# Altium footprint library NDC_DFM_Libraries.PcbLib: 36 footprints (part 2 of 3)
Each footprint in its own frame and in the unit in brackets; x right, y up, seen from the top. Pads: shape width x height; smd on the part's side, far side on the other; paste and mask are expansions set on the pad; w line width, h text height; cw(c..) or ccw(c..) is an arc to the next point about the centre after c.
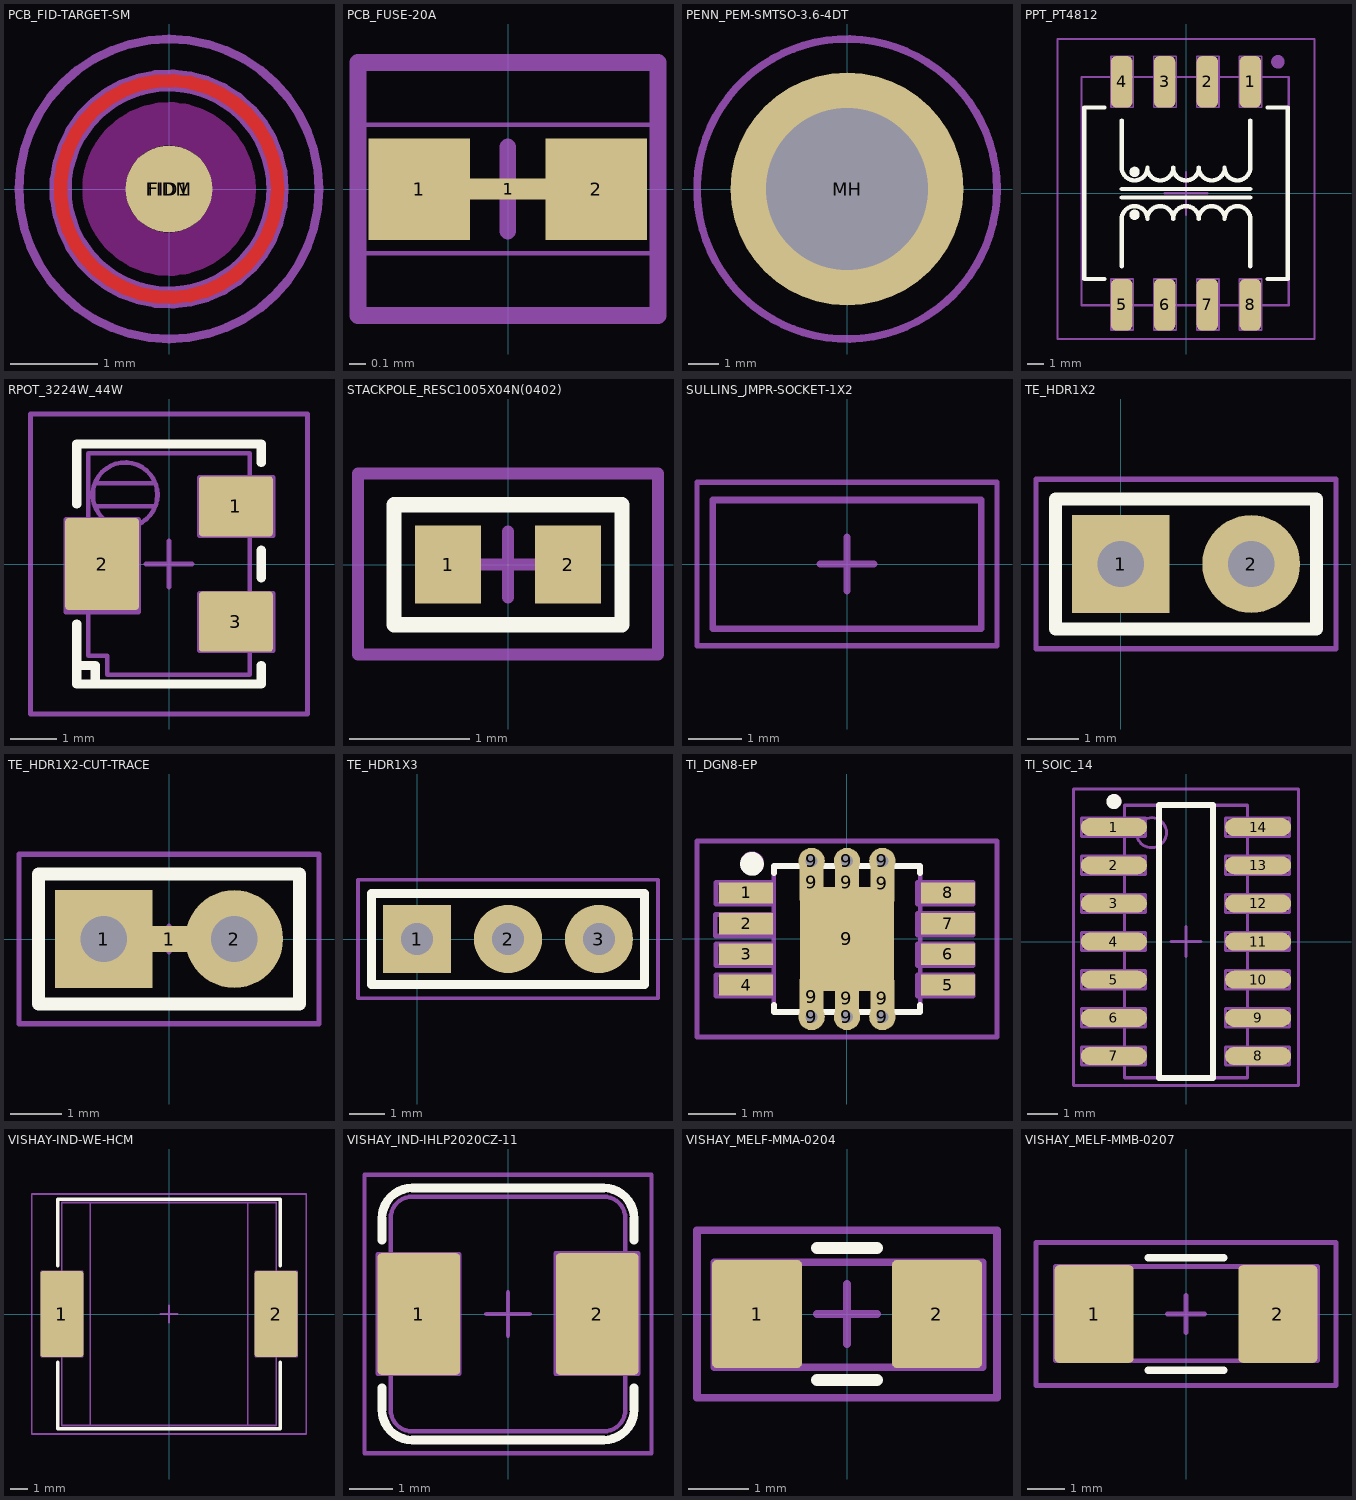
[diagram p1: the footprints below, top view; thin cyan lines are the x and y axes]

## PCB_FID-TARGET-SM [mm]
pads (2):
  round 1 on Mech6 paste-0.55 mask+1: FID1(0,0)
  round 1 all layers, no hole paste-0.762 mask+0.9: FIDM(0,0)
Top Layer:
  circle w0.155: c0,0 r1.25
Bottom Layer:
  circle w0.155: c0,0 r1.25
Keep-Out Layer:
  circle w0.5: c0,0 r0.75
M06 - ASSY TOP:
  circle w0.254: c0,0 r1.25
  text ".designator" at -1.194,-2.819 h0.89
M15 - COURTYARD TOP:
  circle w0.1: c0,0 r1.727
  lines w0.1: -0.381,0 0.381,0 ; 0,-0.381 0,0.381

## PCB_FUSE-20A [mm]
pads (3):
  rect 0.6x0.6 smd: 1(-0.527,-0.001) 2(0.523,-0.001)
  rrect10% 1x0.125 smd paste-2 mask-2: 1(0,0)
M06 - ASSY TOP:
  lines w0.025: -0.889,-0.381 0.889,-0.381 0.889,0.381 -0.889,0.381 -0.889,-0.381
  text "DNP" at -0.254,-0.711 h0.25
  text ".designator" at -0.737,-0.254 h0.89
M15 - COURTYARD TOP:
  lines w0.1: -0.254,0 0.254,0 ; -0.002,-0.249 -0.002,0.249 ; -0.889,-0.75 0.889,-0.75 0.889,0.75 -0.889,0.75 -0.889,-0.75

## PENN_PEM-SMTSO-3.6-4DT [mm] "PEM Standoff SMTSO-3.6-4DT, Matte Tin, Surface Mount Solder, ReelFast"
height 4
pads (1):
  round 7.77 hole 5.41: MH(0,0)
M06 - ASSY TOP:
  circle w0.254: c0,0 r2.7
  circle w0.254: c0,0 r3.57
  text ".designator" at -1.88,-0.432 h0.89
M15 - COURTYARD TOP:
  circle w0.254: c0,0 r5
  lines w0.1: -0.5,0 0.5,0 ; 0,-0.5 0,0.5
3D body: height 4, standoff -1.53, extent -3.57,-3.57 3.57,3.57

## PPT_PT4812 [mm] "Transformer for Digital Audio Data Transmission"
height 9.15
pads (8):
  rrect50% 1.27x3.05 smd: 1(3.81,6.605) 2(1.27,6.605) 3(-1.27,6.605) 4(-3.81,6.605) 5(-3.81,-6.605) 6(-1.27,-6.605) 7(1.27,-6.605) 8(3.81,-6.605)
Top Overlay:
  circle w0.254: c-3.048,1.271 r0.18
  circle w0.254: c-3.048,-1.269 r0.18
  lines w0.254: -4.826,-5.081 -6.03,-5.081 -6.03,5.081 -4.826,5.081 ; -3.81,-4.317 -3.81,-1.523 cw(c-3.048,-1.523) -3.048,-0.761 cw(c-3.048,-1.523) -2.286,-1.523 cw(c-1.524,-1.523) -1.524,-0.761 cw(c-1.524,-1.523) -0.762,-1.523 cw(c0,-1.523) 0,-0.761 cw(c0,-1.523) 0.762,-1.523 cw(c1.524,-1.523) 1.524,-0.761 cw(c1.524,-1.523) 2.286,-1.523 cw(c3.048,-1.523) 3.048,-0.761 cw(c3.048,-1.523) 3.81,-1.523 3.81,-4.317 ; -3.81,0.255 3.81,0.255 ; -3.81,4.319 -3.81,1.525 ccw(c-3.048,1.525) -3.048,0.763 ccw(c-3.048,1.525) -2.286,1.525 ccw(c-1.524,1.525) -1.524,0.763 ccw(c-1.524,1.525) -0.762,1.525 ccw(c0,1.525) 0,0.763 ccw(c0,1.525) 0.762,1.525 ccw(c1.524,1.525) 1.524,0.763 ccw(c1.524,1.525) 2.286,1.525 ccw(c3.048,1.525) 3.048,0.763 ccw(c3.048,1.525) 3.81,1.525 3.81,4.319 ; -3.228,-1.269 -2.921,-1.269 ; -3.228,1.271 -2.921,1.271 ; 3.302,-0.253 -3.81,-0.253 3.81,-0.253 ; 4.826,-5.081 6.03,-5.081 6.03,5.081 4.826,5.081
M06 - ASSY TOP:
  circle w0.4: c5.448,7.791 r0.2
  lines w0.1: -4.445,-8.105 -4.445,-5.082 -3.124,-5.082 -3.124,-8.105 -4.445,-8.105 ; -4.445,5.105 -3.124,5.105 -3.124,8.128 -4.445,8.128 -4.445,5.105 ; -1.905,-8.105 -1.905,-5.082 -0.584,-5.082 -0.584,-8.105 -1.905,-8.105 ; -1.905,5.105 -1.905,8.128 -0.584,8.128 -0.584,5.105 -1.905,5.105 ; 0.635,-8.105 0.635,-5.082 1.956,-5.082 1.956,-8.105 0.635,-8.105 ; 0.635,5.105 0.635,8.128 1.956,8.128 1.956,5.105 0.635,5.105 ; 3.175,-8.105 3.175,-5.082 4.496,-5.082 4.496,-8.105 3.175,-8.105 ; 3.175,5.105 3.175,8.128 4.496,8.128 4.496,5.105 3.175,5.105
  lines w0.127: -6.198,-6.638 -6.198,6.894 6.091,6.894 6.091,-6.638 -6.198,-6.638
  text ".designator" at -4.115,-0.483 h0.89
M15 - COURTYARD TOP:
  lines w0.127: -1.27,0 1.27,0 ; 0,-1.27 0,1.27 ; -7.62,-8.635 -7.62,9.145 7.62,9.145 7.62,-8.635 -7.62,-8.635
3D body: height 8.86, standoff 0.02, extent -5.969,-6.638 6.091,6.894

## RPOT_3224W_44W [mm] "Potentiometer, SMT 4mm, Multiturn Cermet, Sealed"
height 5.3
pads (3):
  rrect10% 1.6x1.3 smd: 1(1.45,1.25) 3(1.45,-1.25)
  rrect10% 1.6x2 smd: 2(-1.45,0)
Top Overlay:
  lines w0.2: -2,-2.2 -1.6,-2.2 -1.6,-2.6 ; -2,-1.3 -2,-2.6 2,-2.6 2,-2.2 ; -2,1.3 -2,2.6 2,2.6 2,2.2 ; 2,-0.3 2,0.3
M06 - ASSY TOP:
  circle w0.1: c-0.95,1.5 r0.7
  lines w0.1: -1.6,1.25 -0.3,1.25 ; -1.6,1.75 -0.3,1.75 ; -2.235,-1.041 -2.235,0.965 -0.66,0.965 -0.66,-1.041 -2.235,-1.041 ; -1.75,-1.988 -1.75,2.4 1.75,2.4 1.75,-2.4 -1.338,-2.4 -1.338,-1.988 -1.75,-1.988 ; 0.66,-1.88 0.66,-0.635 2.261,-0.635 2.261,-1.88 0.66,-1.88 ; 0.66,0.61 2.261,0.61 2.261,1.88 0.66,1.88 0.66,0.61
  text ".designator" at -1.448,-0.457 h0.89
M15 - COURTYARD TOP:
  lines w0.1: -0.5,0 0.5,0 ; 0,-0.5 0,0.5 ; -3,-3.25 -3,3.25 3,3.25 3,-3.25 -3,-3.25
3D body: height 5.28, standoff 0, extent -1.965,-2.413 1.973,2.413

## STACKPOLE_RESC1005X04N(0402) [mm] "Chip Resistor, Body 1.0x0.5mm, Height 0.40mm, IPC Medium Density"
height 0.4
pads (2):
  rect 0.55x0.65 smd: 1(-0.5,0) 2(0.5,0)
Top Overlay:
  lines w0.127: -0.95,-0.5 -0.95,0.5 0.95,0.5 0.95,-0.5 -0.95,-0.5
M06 - ASSY TOP:
  lines w0.1: -0.95,-0.508 0.95,-0.508 0.95,0.5 -0.95,0.5 -0.95,-0.508
  text ".designator" at -0.711,-0.279 h0.89
M15 - COURTYARD TOP:
  lines w0.1: -0.275,0 0.275,0 ; 0,-0.275 0,0.275 ; -1.25,-0.75 1.25,-0.75 1.25,0.762 -1.25,0.762 -1.25,-0.75
3D body: height 0.4, standoff 0.39, extent 0.225,-0.206 0.475,0.206
3D body: height 0.01, standoff 0, extent -0.525,-0.275 -0.225,0.275
3D body: height 0.39, standoff 0.01, extent -0.475,-0.275 0.475,0.275
3D body: height 0.4, standoff 0.39, extent -0.475,-0.206 -0.225,0.206
3D body: height 0.4, standoff 0, extent 0.475,-0.275 0.525,0.275
3D body: height 0.01, standoff 0, extent 0.225,-0.275 0.525,0.275
3D body: height 0.45, standoff 0.39, extent -0.525,-0.275 0.525,0.275
3D body: height 0.4, standoff 0, extent -0.525,-0.275 -0.475,0.275
3D body: height 0.4, standoff 0.39, extent -0.225,-0.275 0.225,0.275

## SULLINS_JMPR-SOCKET-1X2 [mm]
height 1.1
M06 - ASSY TOP:
  lines w0.127: -2.5,-1.208 2.5,-1.208 2.5,1.193 -2.5,1.193 -2.5,-1.208
  text ".designator" at -2.184,-0.787 h0.89
M15 - COURTYARD TOP:
  lines w0.1: -2.794,-1.524 -2.794,1.524 2.794,1.524 2.794,-1.524 -2.794,-1.524
  lines w0.127: -0.5,0 0.5,0 ; 0,-0.5 0,0.5
3D body: height 16.56, standoff 2.74, extent -2.5,-1.208 2.5,1.193

## TE_HDR1X2 [mm] "Connector; Header; 2 Position"
pads (2):
  rect 1.905x1.905 hole 0.9: 1(0,0)
  round 1.905 hole 0.9: 2(2.54,0)
Top Overlay:
  lines w0.254: -1.27,-1.27 -1.27,1.27 3.81,1.27 3.81,-1.27 -1.27,-1.27
M06 - ASSY TOP:
  lines w0.1: -1.27,-1.27 -1.27,1.245 3.81,1.245 3.81,-1.27 -1.27,-1.27
  text ".designator" at -0.94,-0.838 h0.89
M15 - COURTYARD TOP:
  lines w0.1: -0.254,0 0.254,0 ; 0,-0.254 0,0.254 ; -1.651,-1.651 -1.651,1.651 4.191,1.651 4.191,-1.651 -1.651,-1.651
3D body: height 8.25, standoff -2.67, extent -1.27,-1.27 3.81,1.27

## TE_HDR1X2-CUT-TRACE [mm] "Connector; Header; 2 Position"
pads (3):
  rect 1.905x1.905 hole 0.9: 1(-1.27,0)
  rrect10% 2.54x0.508 smd paste-2.667 mask-2.667: 1(0,0)
  round 1.905 hole 0.9: 2(1.27,0)
Top Overlay:
  lines w0.254: -2.54,-1.27 -2.54,1.27 2.54,1.27 2.54,-1.27 -2.54,-1.27
M06 - ASSY TOP:
  lines w0.1: -2.54,-1.27 2.54,-1.27 2.54,1.245 -2.54,1.245 -2.54,-1.27
  text ".designator" at -2.235,-0.787 h0.89
M15 - COURTYARD TOP:
  lines w0.1: -0.254,0 0.254,0 ; 0,-0.254 0,0.254 ; -2.921,-1.651 2.921,-1.651 2.921,1.651 -2.921,1.651 -2.921,-1.651
3D body: height 8.25, standoff -2.67, extent -2.54,-1.27 2.54,1.27

## TE_HDR1X3 [mm] "Connector; Header; 3 Position"
pads (3):
  rect 1.905x1.905 hole 0.9: 1(0,0)
  round 1.905 hole 0.9: 2(2.54,0) 3(5.08,0)
Top Overlay:
  lines w0.254: -1.27,-1.27 6.35,-1.27 6.35,1.27 -1.27,1.27 -1.27,-1.27
M06 - ASSY TOP:
  lines w0.1: -1.27,-1.27 -1.27,1.245 6.35,1.245 6.35,-1.27 -1.27,-1.27
  text ".designator" at -0.965,-0.838 h0.89
M15 - COURTYARD TOP:
  lines w0.1: -0.254,0 0.254,0 ; 0,-0.254 0,0.254 ; -1.651,-1.651 -1.651,1.651 6.731,1.651 6.731,-1.651 -1.651,-1.651
3D body: height 8.25, standoff -2.67, extent -1.27,-1.27 6.35,1.27

## TI_DGN8-EP [mil] "TSOP, 8-Leads, Body 3.1x3.1mm (max), Pitch 0.65mm, IPC Medium Density"
height 43.31
pads (21):
  rect 45x17.72 smd mask+0: 1(-84,38.39) 2(-84,12.8) 3(-84,-12.8) 4(-84,-38.39) 5(84,-38.39) 6(84,-12.8) 7(84,12.8) 8(84,38.39)
  round 22 hole 10: 9(-29.53,-65) 9(-29.53,65) 9(0,-65) 9(0,65) 9(29.53,-65) 9(29.53,65)
  rect 20x30 smd: 9(-29.53,-48.23) 9(-29.53,47.24) 9(0,-49.21) 9(0,47.24) 9(29.53,-49.21) 9(29.53,46.26)
  rect 78.74x86.61 smd: 9(0,0)
Top Overlay:
  circle w9.84: c-79.2,62.59 r4.92
  lines w5: -61.02,-55.08 -61.02,-61.02 61.02,-61.02 61.02,-55.08 ; -61.02,55.08 -61.02,61.02 61.02,61.02 61.02,55.08
M06 - ASSY TOP:
  circle w10: c-79,63 r5
  lines w3.94: -61.02,-61.02 61.02,-61.02 ; -61.02,-61.02 -61.02,61.02 61.02,61.02 61.02,-61.02 ; -61.02,-61.02 61.02,-61.02 ; -109.9,2.43 -109.9,20.43 -63.64,20.43 -63.64,2.43 -109.9,2.43 ; -109.25,-47.77 -109.25,-29.77 -62.99,-29.77 -62.99,-47.77 -109.25,-47.77 ; -109.25,-22.18 -109.25,-4.18 -62.99,-4.18 -62.99,-22.18 -109.25,-22.18 ; -109.25,29 -62.99,29 -62.99,47 -109.25,47 -109.25,29 ; 58.75,-47.77 58.75,-29.77 105.01,-29.77 105.01,-47.77 58.75,-47.77 ; 58.75,-22.18 58.75,-4.18 105.01,-4.18 105.01,-22.18 58.75,-22.18 ; 58.75,3.41 58.75,21.41 105.01,21.41 105.01,3.41 58.75,3.41 ; 58.75,29 58.75,47 105.01,47 105.01,29 58.75,29
  text ".designator" at -40,-38 h35
M15 - COURTYARD TOP:
  lines w3.94: -19.68,0 19.69,0 ; 0,-19.69 0,19.68 ; -125,-81.69 125,-81.69 125,81.69 -125,81.69 -125,-81.69
3D body: height 38, standoff 0, extent -96.49,-59 96.51,59

## TI_SOIC_14 [mm] "SOIC, 14-Leads, Body 8.65x3.95mm, Pitch 1.27mm, IPC Medium Density"
height 1.75
pads (14):
  oval 2.2x0.6 smd: 1(-2.4,3.81) 2(-2.4,2.54) 3(-2.4,1.27) 4(-2.4,0) 5(-2.4,-1.27) 6(-2.4,-2.54) 7(-2.4,-3.81) 8(2.4,-3.81) 9(2.4,-2.54) 10(2.4,-1.27) 11(2.4,0) 12(2.4,1.27) 13(2.4,2.54) 14(2.4,3.81)
Top Overlay:
  circle w0.25: c-2.4,4.66 r0.125
  lines w0.2: -0.9,-4.55 0.9,-4.55 0.9,4.55 -0.9,4.55 -0.9,-4.55
M06 - ASSY TOP:
  circle w0.254: c-2.388,4.674 r0.114
  lines w0.1: -3.48,-4.115 -1.346,-4.115 -1.346,-3.505 -3.48,-3.505 -3.48,-4.115 ; -3.48,-2.845 -1.346,-2.845 -1.346,-2.235 -3.48,-2.235 -3.48,-2.845 ; -3.48,-1.575 -1.346,-1.575 -1.346,-0.965 -3.48,-0.965 -3.48,-1.575 ; -3.48,-0.305 -1.346,-0.305 -1.346,0.305 -3.48,0.305 -3.48,-0.305 ; -3.48,0.965 -1.346,0.965 -1.346,1.575 -3.48,1.575 -3.48,0.965 ; -3.48,2.235 -1.346,2.235 -1.346,2.845 -3.48,2.845 -3.48,2.235 ; -3.48,3.505 -3.48,4.115 -1.346,4.115 -1.346,3.505 -3.48,3.505 ; -2.05,-4.55 -2.05,4.55 2.05,4.55 2.05,-4.55 -2.05,-4.55 ; 1.32,-4.115 3.454,-4.115 3.454,-3.505 1.32,-3.505 1.32,-4.115 ; 1.32,-2.845 3.454,-2.845 3.454,-2.235 1.32,-2.235 1.32,-2.845 ; 1.32,-1.575 3.454,-1.575 3.454,-0.965 1.32,-0.965 1.32,-1.575 ; 1.32,-0.305 3.454,-0.305 3.454,0.305 1.32,0.305 1.32,-0.305 ; 1.32,0.965 3.454,0.965 3.454,1.575 1.32,1.575 1.32,0.965 ; 1.32,2.235 3.454,2.235 3.454,2.845 1.32,2.845 1.32,2.235 ; 1.32,3.505 3.454,3.505 3.454,4.115 1.32,4.115 1.32,3.505
  text ".designator" at 0.279,-4.14 h0.89
M13 - 3D TOP:
  circle w0.1: c-1.15,3.625 r0.5
  lines w0.1: -2.05,-4.525 -2.05,4.525 2.05,4.525 2.05,-4.525 -2.05,-4.525
M15 - COURTYARD TOP:
  lines w0.1: -0.5,0 0.5,0 ; 0,-0.5 0,0.5 ; -3.75,-4.8 3.75,-4.8 3.75,5.08 -3.75,5.08 -3.75,-4.8
3D body: height 1.75, standoff 0, extent -2.9,-4.265 2.9,4.265

## VISHAY-IND-WE-HCM [mm] "WE-HCM SMD High-Current Flat Wire Inductor"
height 9.5
pads (2):
  rrect10% 2.5x5 smd: 1(-6.25,0) 2(6.25,0)
Top Overlay:
  lines w0.2: -6.5,-2.8 -6.5,-6.7 6.5,-6.7 6.5,-2.8 ; -6.5,2.8 -6.5,6.7 6.5,6.7 6.5,2.8
M06 - ASSY TOP:
  lines w0.1: -4.6,-6.5 -4.6,6.5 ; 4.6,-6.5 4.6,6.5 ; -7.442,-2.5 -7.442,2.5 -5.029,2.5 -5.029,-2.5 -7.442,-2.5 ; -6.25,-6.5 -6.25,6.5 6.25,6.5 6.25,-6.5 -6.25,-6.5 ; 5.029,-2.5 5.029,2.5 7.468,2.5 7.468,-2.5 5.029,-2.5
  text ".designator" at -4.318,-0.66 h0.89
M15 - COURTYARD TOP:
  lines w0.1: -0.5,0 0.5,0 ; 0,-0.5 0,0.5 ; -8,-7 -8,7 8,7 8,-7 -8,-7
3D body: height 5.02, standoff 0, extent 5.19,-2.5 7,2.5
3D body: height 4.5, standoff 0.5, extent -6.25,-6.5 6.25,6.5
3D body: height 5.2, standoff 4.5, extent -6.25,-6.5 6.25,6.5
3D body: height 5.01, standoff -0.01, extent -7,-2.5 -5.19,2.5
3D body: height 9, standoff 5.3, extent -6.25,-6.5 6.25,6.5
3D body: height 0.5, standoff 0.1, extent -4.6,-6.5 4.6,6.5

## VISHAY_IND-IHLP2020CZ-11 [mm] "Low Profile, High Current IHLP® Inductor"
height 3
pads (2):
  rrect10% 1.9x2.8 smd: 1(-2.05,0) 2(2.05,0)
Top Overlay:
  lines w0.2: -2.9,-1.7 -2.9,-2.2 ccw(c-2.2,-2.2) -2.2,-2.9 2.2,-2.9 ccw(c2.2,-2.2) 2.9,-2.2 2.9,-1.7 ; -2.9,1.7 -2.9,2.2 cw(c-2.2,2.2) -2.2,2.9 2.2,2.9 cw(c2.2,2.2) 2.9,2.2 2.9,1.7
M06 - ASSY TOP:
  lines w0.1: -2.997,-1.372 -1.118,-1.372 -1.118,1.372 -2.997,1.372 -2.997,-1.372 ; -2.7,-2.2 ccw(c-2.2,-2.2) -2.2,-2.7 2.2,-2.7 ccw(c2.2,-2.2) 2.7,-2.2 2.7,2.2 ccw(c2.2,2.2) 2.2,2.7 -2.2,2.7 ccw(c-2.2,2.2) -2.7,2.2 -2.7,-2.2 ; 1.092,-1.372 1.092,1.397 2.997,1.397 2.997,-1.372 1.092,-1.372
  text ".designator" at -2.159,-2.413 h0.89
M15 - COURTYARD TOP:
  lines w0.1: -0.5,0 0.5,0 ; 0,-0.5 0,0.5 ; -3.3,-3.2 -3.3,3.2 0,3.2 3.3,3.2 3.3,-3.2 -3.3,-3.2
3D body: height 3, standoff 0, extent -2.75,-2.6 2.75,2.6

## VISHAY_MELF-MMA-0204 [mm]
pads (2):
  rrect10% 1.5x1.8 smd: 1(-1.5,0) 2(1.5,0)
Top Overlay:
  lines w0.2: -0.5,-1.1 0.5,-1.1 ; -0.5,1.1 0.5,1.1
M06 - ASSY TOP:
  lines w0.127: -2.21,-0.889 2.261,-0.889 2.261,0.864 -2.21,0.864 -2.21,-0.889
  text ".designator" at -1.93,-0.508 h0.89
M15 - COURTYARD TOP:
  lines w0.127: -0.5,0 0.5,0 ; 0,-0.5 0,0.5 ; -2.5,-1.397 -2.5,1.397 2.5,1.397 2.5,-1.397 -2.5,-1.397
3D body: height 1.4, standoff 0, extent -1.7,-0.7 1.7,0.7

## VISHAY_MELF-MMB-0207 [mm]
pads (2):
  rrect10% 2.1x2.6 smd: 1(-2.45,0) 2(2.45,0)
Top Overlay:
  lines w0.2: -1,-1.5 1,-1.5 ; -1,1.5 1,1.5
M06 - ASSY TOP:
  lines w0.127: -3.48,-1.245 3.505,-1.245 3.505,1.27 -3.48,1.27 -3.48,-1.245
  text ".designator" at -3.124,-0.94 h0.89
M15 - COURTYARD TOP:
  lines w0.127: -0.5,0 0.5,0 ; 0,-0.5 0,0.5 ; -4,-1.905 -4,1.905 4,1.905 4,-1.905 -4,-1.905
3D body: height 2.2, standoff 0, extent -2.65,-1.1 2.65,1.1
